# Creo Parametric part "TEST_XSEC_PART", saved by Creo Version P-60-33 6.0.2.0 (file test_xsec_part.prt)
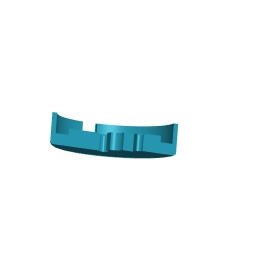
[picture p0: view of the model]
Units: Inch lbm Second (Pro/E Default); INCH, POUND, SECS

Created from: INLBS_PART_SOLID.PRT

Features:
  1. datum plane "RIGHT"
  2. datum plane "TOP"
  3. datum plane "FRONT"
  4. coordinate system
  5. extrusion "Extrude 1"
  6. revolved cut "Revolve 1"
  7. pattern "Pattern 1"
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
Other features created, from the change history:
  extruded cut "Extrude 2"
  datum axis "A_3"
  extruded cut "Extrude 2 [2]"
  extruded cut "Extrude 2 [3]"
  extruded cut "Extrude 2 [4]"
  hole "Hole 1"
  chamfer "Chamfer 1" (2 times)
  group "LOCAL_GROUP"
  pattern "Pattern 2" (2 times)
  group "LOCAL_GROUP_1"
  hole "Hole 2"
  chamfer "Chamfer 2"
  group "LOCAL_GROUP_2"
  hole "Hole 3"
  chamfer "Chamfer 3"
  group "LOCAL_GROUP_3"
  hole "Hole 4"
  chamfer "Chamfer 4"
  hole "Hole 1 [2]"
  hole "Hole 1 [3]"
  hole "Hole 1 [4]"
  round "Round 1"
  planar section "XSEC0001"
  planar section "Y"

Family table entries: d22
